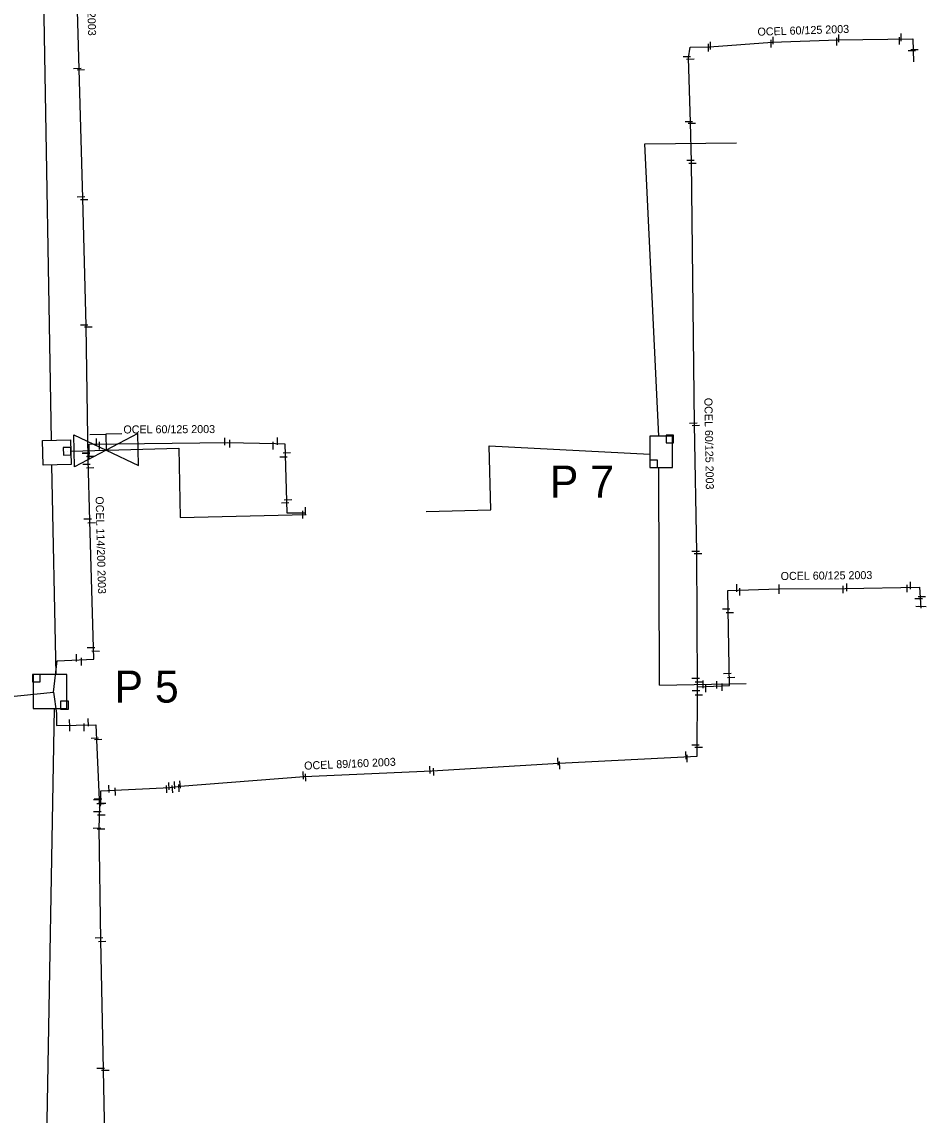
# Model space of a CAD drawing. Extents: x -642943 to -623314, y -1138561 to -1113539.
# Drawn here: x -641308 to -641223.3, y -1114765.3 to -1114662.9 of the extents above; entities that cross this region are included whole.
import ezdxf

# ---------------------------------------------------------------- set-up
doc = ezdxf.new("R2010")
doc.units = 0
for name, color, linetype in [('horkovod armatury', 7, 'Continuous'), ('horkovod dimenze', 7, 'Continuous'), ('horkovod předisol', 7, 'Continuous'), ('horkovod sváry', 7, 'Continuous'), ('horkovod trasa', 7, 'Continuous'), ('horkovod zrušený', 7, 'Continuous'), ('horkovod číslo šachty', 7, 'Continuous'), ('horkovod šachty', 7, 'Continuous')]:
    doc.layers.add(name, color=color, linetype=linetype)

# ---------------------------------------------------------------- blocks, each defined once
blk = doc.blocks.new('POINT_DISPLAY')
blk.add_line((0, 0), (0, 0))
blk = doc.blocks.new('SPH')
at = {"layer": 'horkovod sváry'}
blk.add_line((0, -0.035), (0, 0.035), dxfattribs=at)
blk = doc.blocks.new('SCH_01_48')
at = {"layer": 'horkovod armatury'}
for p, q in [((10, 5), (-10, -5)), ((-10, -5), (-10, 5)), ((-10, 5), (10, -5)), ((-5, 5), (0, 5)), ((0, 5), (0, 0)), ((5, 5), (0, 5)), ((10, -5), (10, 5))]:
    blk.add_line(p, q, dxfattribs=at)

msp = doc.modelspace()

# ---------------------------------------------------------------- linework, layer by layer
at = {"layer": 'horkovod předisol'}
for points in [[(-641301.77, -1114703.9), (-641301.96, -1114691.39), (-641302.29, -1114679.42), (-641302.63, -1114667.33), (-641302.97, -1114655.27), (-641302.97, -1114652.76)], [(-641244.69, -1114725.18), (-641244.77, -1114712.58), (-641244.97, -1114700.58), (-641245.26, -1114676.02), (-641245.36, -1114672.32), (-641245.53, -1114666.26), (-641245.37, -1114665.28), (-641243.57, -1114665.24), (-641237.7, -1114664.8), (-641231.56, -1114664.59), (-641224.52, -1114664.5), (-641224.47, -1114666.66)], [(-641301.77, -1114703.9), (-641301.68, -1114703.8), (-641301.68, -1114702.46), (-641288.74, -1114702.32), (-641284.24, -1114702.39), (-641283.35, -1114702.42), (-641283.33, -1114703.47), (-641283.2, -1114707.81), (-641283.18, -1114708.9), (-641281.38, -1114708.9)], [(-641305.03, -1114725.69), (-641304.7, -1114722.76), (-641301.24, -1114722.6), (-641301.64, -1114709.63), (-641301.77, -1114703.9)], [(-641244.69, -1114725.18), (-641241.69, -1114725.08), (-641241.85, -1114716.17), (-641237.05, -1114716.03), (-641230.85, -1114715.97), (-641223.88, -1114715.85), (-641223.78, -1114717.82)], [(-641300.73, -1114736.46), (-641300.6, -1114736.25), (-641300.59, -1114734.95), (-641294.09, -1114734.62), (-641293.15, -1114734.5), (-641281.56, -1114733.59), (-641269.57, -1114733.06), (-641257.7, -1114732.36), (-641244.72, -1114731.7), (-641244.69, -1114725.18)], [(-641348.03, -1114728.59), (-641341.23, -1114725.83), (-641339.91, -1114728.35), (-641338.33, -1114728.25), (-641326.92, -1114727.39), (-641315.09, -1114726.66), (-641314.85, -1114727.71), (-641314.72, -1114729.47), (-641314.61, -1114730.24), (-641313.43, -1114730.11), (-641312.23, -1114729.91), (-641312.38, -1114728.04), (-641312.38, -1114726.39), (-641311.51, -1114726.35), (-641305.03, -1114725.69)], [(-641305.03, -1114725.69), (-641304.76, -1114727.69), (-641304.74, -1114728.82), (-641301.08, -1114728.76), (-641300.73, -1114736.47)], [(-641300.73, -1114736.47), (-641300.77, -1114738.44), (-641300.62, -1114748.91), (-641300.39, -1114761.06), (-641299.92, -1114784.63), (-641300.26, -1114793.42), (-641306.19, -1114793.27), (-641306.24, -1114794.33)]]:
    msp.add_lwpolyline(points, dxfattribs=at)
at = {"layer": 'horkovod trasa'}
for points in [[(-641301.77, -1114703.9), (-641301.96, -1114691.39), (-641302.29, -1114679.42), (-641302.63, -1114667.33), (-641302.97, -1114655.27), (-641302.97, -1114652.76)], [(-641244.69, -1114725.18), (-641244.77, -1114712.58), (-641244.97, -1114700.58), (-641245.26, -1114676.02), (-641245.36, -1114672.32), (-641245.53, -1114666.26), (-641245.37, -1114665.28), (-641243.57, -1114665.24), (-641237.7, -1114664.8), (-641231.56, -1114664.59), (-641224.52, -1114664.5), (-641224.47, -1114666.66)], [(-641301.77, -1114703.9), (-641301.68, -1114703.8), (-641301.68, -1114702.46), (-641288.74, -1114702.32), (-641284.24, -1114702.39), (-641283.35, -1114702.42), (-641283.33, -1114703.47), (-641283.2, -1114707.81), (-641283.18, -1114708.9), (-641281.38, -1114708.9)], [(-641305.03, -1114725.69), (-641304.7, -1114722.76), (-641301.24, -1114722.6), (-641301.64, -1114709.63), (-641301.77, -1114703.9)], [(-641244.69, -1114725.18), (-641241.69, -1114725.08), (-641241.85, -1114716.17), (-641237.05, -1114716.03), (-641230.85, -1114715.97), (-641223.88, -1114715.85), (-641223.78, -1114717.82)], [(-641300.73, -1114736.46), (-641300.6, -1114736.25), (-641300.59, -1114734.95), (-641294.09, -1114734.62), (-641293.15, -1114734.5), (-641281.56, -1114733.59), (-641269.57, -1114733.06), (-641257.7, -1114732.36), (-641244.72, -1114731.7), (-641244.69, -1114725.18)], [(-641348.03, -1114728.59), (-641341.23, -1114725.83), (-641339.91, -1114728.35), (-641338.33, -1114728.25), (-641326.92, -1114727.39), (-641315.09, -1114726.66), (-641314.85, -1114727.71), (-641314.72, -1114729.47), (-641314.61, -1114730.24), (-641313.43, -1114730.11), (-641312.23, -1114729.91), (-641312.38, -1114728.04), (-641312.38, -1114726.39), (-641311.51, -1114726.35), (-641305.03, -1114725.69)], [(-641305.03, -1114725.69), (-641304.76, -1114727.69), (-641304.74, -1114728.82), (-641301.08, -1114728.76), (-641300.73, -1114736.47)], [(-641300.73, -1114736.47), (-641300.77, -1114738.44), (-641300.62, -1114748.91), (-641300.39, -1114761.06), (-641299.92, -1114784.63), (-641300.26, -1114793.42), (-641306.19, -1114793.27), (-641306.24, -1114794.33)]]:
    msp.add_lwpolyline(points, dxfattribs=at)
at = {"layer": 'horkovod zrušený'}
for p, q in [((-641306.14, -1114651.31), (-641305.24, -1114702.1)), ((-641249.64, -1114674.33), (-641241.05, -1114674.25)), ((-641248.32, -1114701.7), (-641249.64, -1114674.33)), ((-641247.64, -1114701.63), (-641247.64, -1114702.33)), ((-641246.94, -1114701.63), (-641247.64, -1114701.63)), ((-641246.94, -1114702.33), (-641246.94, -1114701.63)), ((-641264.2, -1114702.63), (-641249.15, -1114703.4)), ((-641247.64, -1114702.33), (-641246.94, -1114702.33)), ((-641303.42, -1114702.77), (-641304.12, -1114702.79)), ((-641304.12, -1114702.79), (-641304.1, -1114703.49)), ((-641304.1, -1114703.49), (-641303.41, -1114703.47)), ((-641303.41, -1114703.47), (-641303.42, -1114702.77)), ((-641304.77, -1114724.03), (-641305.18, -1114704.42)), ((-641249.15, -1114703.95), (-641249.15, -1114704.65)), ((-641248.45, -1114703.95), (-641249.15, -1114703.95)), ((-641249.15, -1114704.65), (-641248.45, -1114704.65)), ((-641248.45, -1114704.65), (-641248.45, -1114703.95)), ((-641248.26, -1114725.05), (-641248.32, -1114704.65)), ((-641248.26, -1114725.05), (-641240.12, -1114724.88)), ((-641304.97, -1114727.23), (-641305.85, -1114777.51))]:
    msp.add_line(p, q, dxfattribs=at)
for points in [[(-641247.04, -1114704.65), (-641247.04, -1114701.7), (-641249.16, -1114701.7), (-641249.16, -1114704.65), (-641247.04, -1114704.65)], [(-641305.99, -1114704.44), (-641306.05, -1114702.12), (-641303.45, -1114702.05), (-641303.39, -1114704.37), (-641305.99, -1114704.44)], [(-641270.11, -1114708.78), (-641264.05, -1114708.63), (-641264.2, -1114702.63)], [(-641303.41, -1114703.12), (-641293.3, -1114702.83), (-641293.15, -1114709.33), (-641281.36, -1114709.06)]]:
    msp.add_lwpolyline(points, dxfattribs=at)
at = {"layer": 'horkovod šachty'}
for p, q in [((-641306.99, -1114724.03), (-641306.99, -1114724.73)), ((-641306.29, -1114724.03), (-641306.99, -1114724.03)), ((-641306.29, -1114724.73), (-641306.29, -1114724.03)), ((-641306.99, -1114724.73), (-641306.29, -1114724.73)), ((-641304.37, -1114726.54), (-641304.37, -1114727.29)), ((-641303.62, -1114726.54), (-641304.37, -1114726.54)), ((-641304.37, -1114727.29), (-641303.62, -1114727.29)), ((-641303.62, -1114727.29), (-641303.62, -1114726.54))]:
    msp.add_line(p, q, dxfattribs=at)
msp.add_lwpolyline([(-641306.93, -1114724.03), (-641306.93, -1114727.23), (-641303.78, -1114727.23), (-641303.78, -1114724.03), (-641306.93, -1114724.03)], dxfattribs=at)

# ---------------------------------------------------------------- block references
at = {"layer": 'horkovod armatury', "xscale": 0.3000444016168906, "yscale": 0.3000444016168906, "rotation": 1.1916372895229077}
msp.add_blockref('SCH_01_48', (-641300.09, -1114703.02), dxfattribs=at)
at = {"layer": 'horkovod sváry', "xscale": 10, "yscale": 10}
for p in [(-641243.48, -1114665.14), (-641237.78, -1114664.95), (-641237.61, -1114664.65), (-641231.63, -1114664.76), (-641231.45, -1114664.45), (-641225.78, -1114664.68), (-641225.62, -1114664.36), (-641243.66, -1114665.32), (-641300.99, -1114702.27), (-641300.72, -1114702.6), (-641288.99, -1114702.22), (-641288.52, -1114702.42), (-641284.44, -1114702.61), (-641284.06, -1114702.18), (-641281.66, -1114709.07), (-641281.42, -1114708.73), (-641241, -1114715.94), (-641240.73, -1114716.29), (-641237.04, -1114715.95), (-641237.03, -1114716.12), (-641231.05, -1114716.07), (-641230.71, -1114715.88), (-641225.04, -1114715.99), (-641224.74, -1114715.71), (-641302.87, -1114722.48), (-641302.4, -1114722.84), (-641244.17, -1114724.96), (-641243.9, -1114725.35), (-641242.88, -1114725), (-641242.37, -1114725.22)]:
    msp.add_blockref('SPH', p, dxfattribs=at)
at = {"layer": 'horkovod sváry'}
for p, xscale, yscale, rotation in [((-641224.61, -1114665.6), 10.000035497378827, 10.000035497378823, -90.2321199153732), ((-641224.36, -1114665.5), 10.000012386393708, 10.00001238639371, -89.90982007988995), ((-641245.69, -1114666.15), 10.000000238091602, 10.000000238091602, -88.18275525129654), ((-641245.37, -1114666.39), 10.000020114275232, 10.000020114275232, -88.05729334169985), ((-641302.8, -1114667.25), 9.999992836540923, 9.999992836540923, -88.47716509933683), ((-641302.48, -1114667.38), 9.999995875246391, 9.999995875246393, -89.01223960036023), ((-641245.51, -1114672.23), 9.999996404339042, 9.999996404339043, -89.6536852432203), ((-641245.23, -1114672.39), 10.000019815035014, 10.000019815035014, -90.53681788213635), ((-641245.35, -1114675.87), 9.999987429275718, 9.99998742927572, -89.77001342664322), ((-641245.17, -1114676.15), 10.000009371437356, 10.000009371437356, -89.92155946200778), ((-641302.45, -1114679.28), 9.999988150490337, 9.999988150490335, -89.18461629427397), ((-641302.16, -1114679.54), 10.00000741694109, 10.00000741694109, -88.43446308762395), ((-641302.16, -1114691.29), 9.999988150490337, 9.999988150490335, -89.18461629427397), ((-641301.77, -1114691.47), 9.999988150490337, 9.999988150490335, -89.18461629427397), ((-641245.08, -1114700.48), 9.999992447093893, 9.999992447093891, -89.70544607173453), ((-641244.85, -1114700.7), 9.999992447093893, 9.999992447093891, -89.70544607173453), ((-641301.99, -1114703.3), 9.999987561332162, 9.99998756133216, -89.42716001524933), ((-641301.97, -1114703.28), 10.00001280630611, 10.00001280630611, -89.68356840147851), ((-641301.59, -1114703.64), 9.999980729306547, 9.999980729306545, 90.9183829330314), ((-641301.57, -1114703.59), 10.000004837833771, 10.000004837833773, -89.15953540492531), ((-641283.48, -1114703.65), 10.000009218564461, 10.000009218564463, -88.74885440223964), ((-641283.17, -1114703.25), 9.999996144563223, 9.999996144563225, -88.16673809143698), ((-641301.94, -1114704.34), 9.99998554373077, 9.999985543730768, -88.95540015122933), ((-641301.6, -1114704.67), 10.000013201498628, 10.00001320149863, -88.31115062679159), ((-641283.06, -1114707.66), 9.999985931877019, 9.99998593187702, -87.01844163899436), ((-641283.33, -1114707.95), 9.999983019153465, 9.999983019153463, -87.40843821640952), ((-641301.83, -1114709.46), 9.99998003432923, 9.99998003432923, -88.53107618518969), ((-641301.46, -1114709.82), 9.999999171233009, 9.999999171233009, -88.21692292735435), ((-641244.87, -1114712.48), 9.999992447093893, 9.999992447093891, -89.70544607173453), ((-641244.65, -1114712.7), 10.00000369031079, 10.000003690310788, -89.7478688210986), ((-641223.97, -1114716.96), 10, 10, 90), ((-641223.68, -1114716.72), 10.000008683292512, 10.000008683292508, -89.92449430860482), ((-641242, -1114717.93), 10.000006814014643, 10.000006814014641, 90.6093930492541), ((-641223.88, -1114717.65), 9.999992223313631, 9.999992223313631, -90.75881538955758), ((-641223.62, -1114717.66), 9.999978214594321, 9.999978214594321, -91.02752228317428), ((-641241.66, -1114718.26), 9.999978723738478, 9.99997872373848, 90.61926712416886), ((-641301.52, -1114721.51), 10.000005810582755, 10.000005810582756, -89.64488085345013), ((-641301.08, -1114721.84), 10.000010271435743, 10.000010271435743, -90.50133194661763), ((-641241.9, -1114723.92), 9.999985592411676, 9.999985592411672, -88.0474091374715), ((-641244.86, -1114724.41), 10.000007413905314, 10.000007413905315, 89.7430663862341), ((-641244.56, -1114724.76), 9.999990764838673, 9.999990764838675, 91.031523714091), ((-641241.54, -1114724.31), 10.00000245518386, 10.000002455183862, -88.66772431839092), ((-641244.83, -1114725.54), 10.000005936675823, 10.000005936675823, -90.06243227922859), ((-641244.57, -1114725.94), 10, 10, -90.00000000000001), ((-641303.52, -1114728.59), 9.999985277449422, 9.99998527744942, 2.3440030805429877), ((-641301.81, -1114728.52), 9.99998527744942, 9.999985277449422, -177.65599691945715), ((-641303.51, -1114729), 10.000003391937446, 10.000003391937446, 0.4308935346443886), ((-641302.18, -1114728.99), 10.000003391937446, 10.000003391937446, -179.56910646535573), ((-641301.15, -1114730), 9.999987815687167, 9.999987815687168, -87.41965669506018), ((-641300.84, -1114730.1), 10.000000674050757, 10.000000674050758, -87.63437108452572), ((-641245.77, -1114731.61), 9.99999166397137, 9.99999166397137, 2.1474821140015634), ((-641244.89, -1114730.62), 10.000003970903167, 10.000003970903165, -89.07334718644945), ((-641244.58, -1114730.85), 10.000006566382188, 10.000006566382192, -88.64397272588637), ((-641257.75, -1114732.18), 10.000009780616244, 10.000009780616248, 2.5533633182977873), ((-641257.6, -1114732.55), 10.00001987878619, 10.000019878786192, 3.2548938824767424), ((-641245.66, -1114731.9), 10.000001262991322, 10.000001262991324, 1.6682986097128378), ((-641281.63, -1114733.49), 10.000005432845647, 10.000005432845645, 2.4174329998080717), ((-641281.42, -1114733.68), 10.000000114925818, 10.000000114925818, 2.709077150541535), ((-641269.76, -1114732.97), 10.000001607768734, 10.000001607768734, 3.5021240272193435), ((-641269.41, -1114733.15), 9.999978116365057, 9.999978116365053, 2.706412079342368), ((-641299.82, -1114734.75), 10.000007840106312, 10.000007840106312, 2.4366595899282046), ((-641294.45, -1114734.78), 9.999983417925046, 9.999983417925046, -177.24257158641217), ((-641294.25, -1114734.49), 10.000021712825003, 10.000021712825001, -177.31096123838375), ((-641293.91, -1114734.78), 10.000008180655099, 10.000008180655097, -176.4067232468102), ((-641293.69, -1114734.4), 10.00001444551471, 10.00001444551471, 2.7886725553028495), ((-641293.27, -1114734.69), 9.999982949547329, 9.99998294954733, 4.556229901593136), ((-641293.17, -1114734.35), 9.999986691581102, 9.999986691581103, 3.822416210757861), ((-641299.23, -1114735.01), 9.999997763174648, 9.999997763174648, 2.593427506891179), ((-641300.93, -1114735.76), 10.000005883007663, 10.000005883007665, -89.41675515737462), ((-641300.86, -1114735.69), 9.999992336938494, 9.999992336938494, -89.48025688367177), ((-641300.63, -1114736.12), 10.000001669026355, 10.000001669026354, -89.82204099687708), ((-641300.48, -1114736.08), 10, 10, -90.00000000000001), ((-641300.92, -1114736.87), 10.000012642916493, 10.000012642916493, -91.27623088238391), ((-641300.55, -1114737.19), 10.000023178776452, 10.000023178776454, -91.37123716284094), ((-641300.96, -1114738.42), 9.999996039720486, 9.999996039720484, -88.60207084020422), ((-641300.58, -1114738.49), 10.000010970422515, 10.000010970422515, -89.21343584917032), ((-641300.77, -1114748.69), 10.00001447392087, 10.000014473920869, -88.67626595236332), ((-641300.48, -1114749.04), 10.000020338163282, 10.00002033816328, -88.58552739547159), ((-641300.61, -1114760.94), 10.000019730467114, 10.000019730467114, 90.44316618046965), ((-641300.18, -1114761.14), 10.00002267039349, 10.000022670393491, 90.84740075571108)]:
    msp.add_blockref('SPH', p, dxfattribs=dict(at, xscale=xscale, yscale=yscale, rotation=rotation))
at = {"layer": 'horkovod zrušený'}
msp.add_blockref('POINT_DISPLAY', (-641303.76, -1114703.13), dxfattribs=at)

# ---------------------------------------------------------------- texts
at = {"layer": 'horkovod dimenze'}
for s, rotation, p in [('OCEL 89/160 2003', 271.7056, (-641302.04, -1114655.63)), ('OCEL 60/125 2003', 1.8497, (-641239.06, -1114664.21)), ('OCEL 60/125 2003', 270.9598, (-641244.05, -1114698.13)), ('OCEL 60/125 2003', 0.2387, (-641298.48, -1114701.46)), ('OCEL 114/200 2003', 271.4737, (-641301.09, -1114707.36)), ('OCEL 60/125 2003', 0.6336, (-641236.9, -1114715.19)), ('OCEL 89/160 2003', 2.5084, (-641281.53, -1114732.96))]:
    msp.add_text(s, height=0.75, rotation=rotation, dxfattribs=at).set_placement(p)
at = {"layer": 'horkovod číslo šachty'}
for s, p in [('P 7', (-641258.53, -1114707.47)), ('P 5', (-641299.32, -1114726.67))]:
    msp.add_text(s, height=3, dxfattribs=at).set_placement(p)

doc.saveas('drawing.dxf')
